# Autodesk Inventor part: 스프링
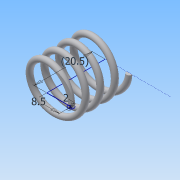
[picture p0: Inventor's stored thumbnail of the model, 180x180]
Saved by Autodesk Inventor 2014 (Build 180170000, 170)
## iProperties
Created: 2017-07
Part Number: 스프링
Material: Generic
Document SubType Name: Modeling
Designer: user
Density: 1 g/cm^3
Appearance: Default
Mass: 0.657231 g
Surface Area: 13.3943 cm^2
Volume: 0.657231 cm^3
Author: user
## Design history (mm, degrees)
sketch "스케치1"
  geometry: L1 (8.5, 0)-(0, 0); L2 (0, 0)-(0, 20.5); L3 (0, 20.5)-(22.973, 20.5); C1 r 1 at (8.5, 0)
  constraints: 6 end point, 2 perpendicular, 1 centre point, 1 coincident, 1 horizontal
  dimensions: "d0" = 20.5 distance of L1.end L2.end (derived); "d1" = 8.5 distance of L1.start L1.end; "d2" = 2 diameter of C1
feature "코일1" sketch "스케치1" pitch "d3" = 10; turns "d5" = 4; dims "d4" = 20.5 (= d0), "d6" = 0, angle "d7" = 90 deg, angle "d8" = 90 deg, "d9" = 0, "d10" = 0
node "작업 평면1"
sketch "스케치2"
  geometry: L1 (-9.5, 0)-(-7.5, 0) reference; L2 (-9.5, 0)-(-7.5, 0) reference; 1 further point
  constraints: 2 horizontal alignment
extrude "돌출1" cut sketch "스케치2" distance "d11" = 10; taper "d12" = 0 deg
node "작업 평면2"
sketch "스케치3"
  geometry: L1 (-7.5, 0)-(-9.5, 0) reference; 1 further point
  constraints: 1 horizontal alignment
extrude "돌출2" cut sketch "스케치3" distance "d13" = 10; taper "d14" = 0 deg
node "솔리드1"
node "절단 모서리 투영1"
node "절단 모서리 투영2"
node "절단 모서리 투영3"
